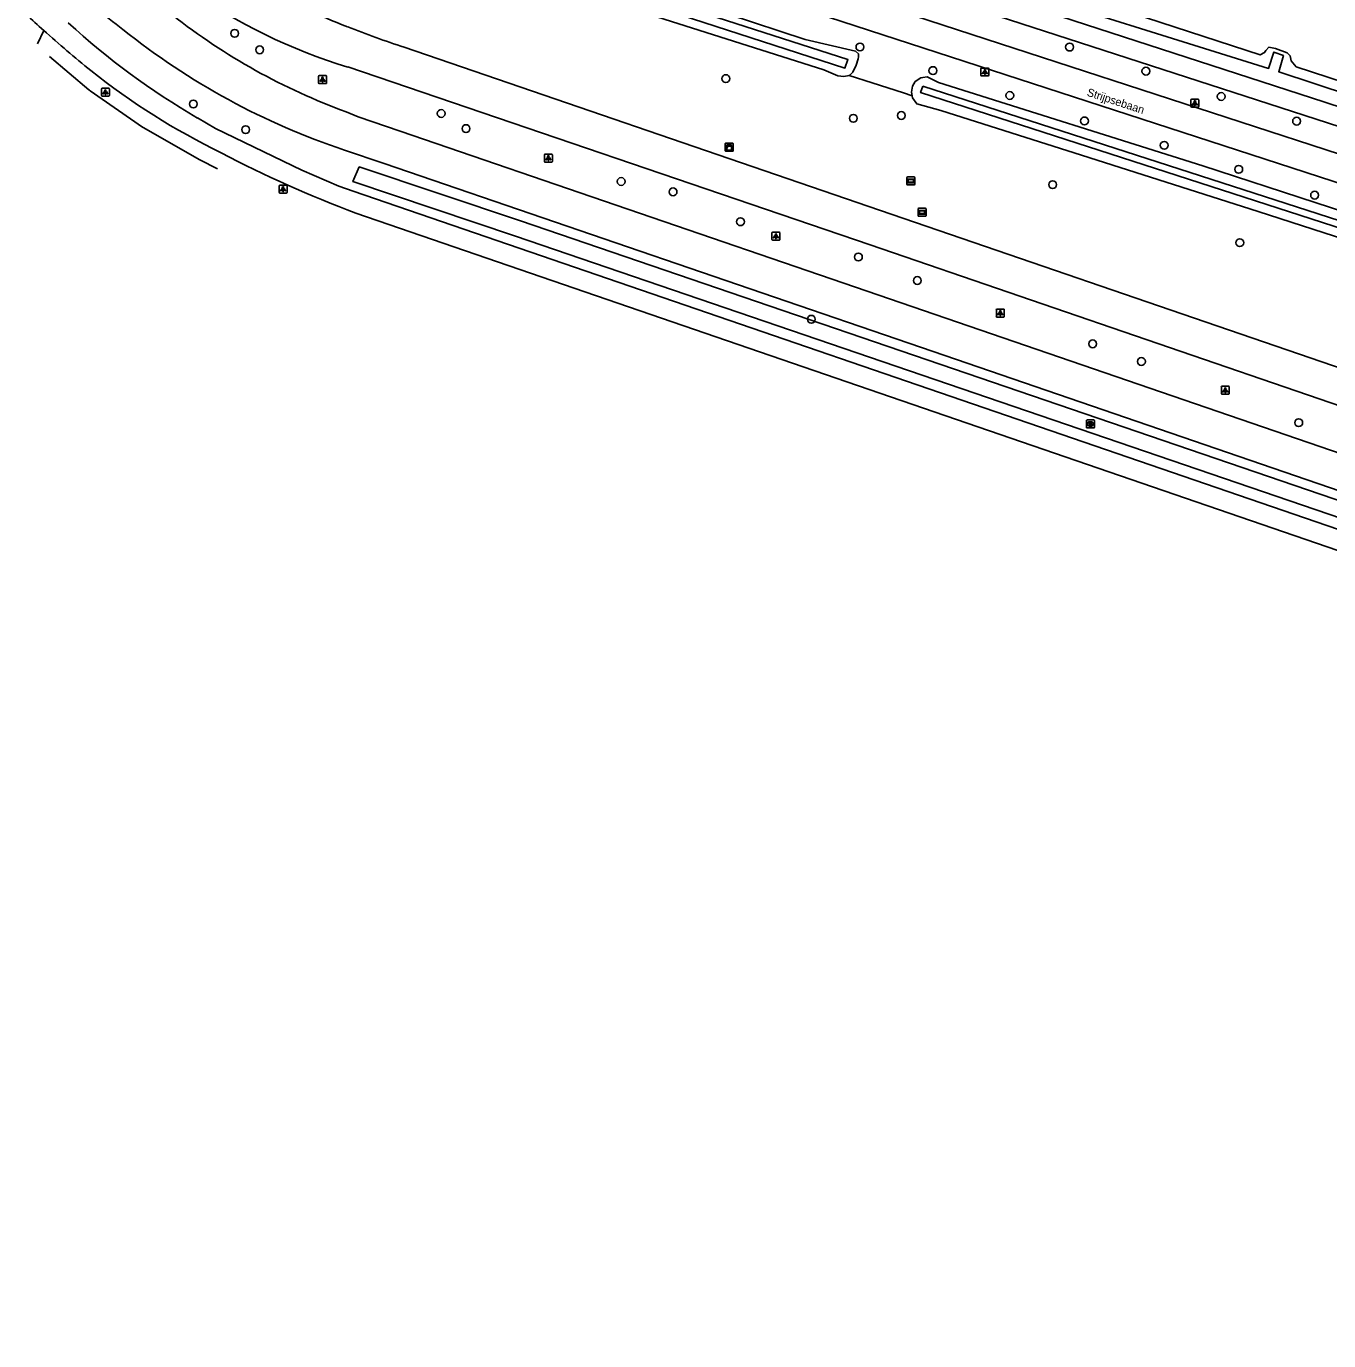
# Model space of a CAD drawing. Extents: x 155275 to 156263, y 382654 to 383635.
# Drawn here: x 155495 to 155657.8, y 382653.9 to 382818.2 of the extents above; entities that cross this region are included whole.
import ezdxf

# ---------------------------------------------------------------- set-up
doc = ezdxf.new("R2010")
doc.units = 0
for name, color, linetype in [('IMGEO_Berm_groen', 7, 'Continuous'), ('IMGEO_Boom', 7, 'Continuous'), ('IMGEO_Fietspad_gesloten', 7, 'Continuous'), ('IMGEO_Kast', 7, 'Continuous'), ('IMGEO_Kolk', 7, 'Continuous'), ('IMGEO_Lichtpunt', 7, 'Continuous'), ('IMGEO_Loofbos', 7, 'Continuous'), ('IMGEO_Muur', 7, 'Continuous'), ('IMGEO_Openbare_ruimte_label', 7, 'Continuous'), ('IMGEO_Rijbaan_regionaal_gesloten', 7, 'Continuous'), ('IMGEO_Verklikker', 7, 'Continuous'), ('IMGEO_Voetpad_open', 7, 'Continuous'), ('IMGEO_Waterloop', 7, 'Continuous')]:
    doc.layers.add(name, color=color, linetype=linetype)

msp = doc.modelspace()

# ---------------------------------------------------------------- linework, layer by layer
at = {"layer": 'IMGEO_Berm_groen'}
for points in [[(155509.58, 382844.19), (155511.11, 382843.85), (155513.91, 382843.18), (155517.02, 382842.15), (155533.94, 382835.74), (155534.62, 382835.53), (155592.37, 382816.51), (155598.66, 382815.05), (155599.06, 382814.71), (155599.04, 382814.32), (155599.02, 382814.11), (155598.74, 382813.29), (155598.34, 382812.43), (155597.96, 382812.03), (155597.87, 382812.01)], [(155597.87, 382812.01), (155597.2, 382811.87), (155596.45, 382811.96), (155594.7, 382812.71), (155573.04, 382819.6), (155561.92, 382822.84), (155552.11, 382826.24), (155542.74, 382829.39), (155531.1, 382833.59), (155523.88, 382835.91), (155514.69, 382838.61), (155507.83, 382840.77)], [(155577.78, 382834.26), (155577.59, 382833.89), (155577.45, 382833.38), (155577.38, 382832.64), (155577.38, 382832.6), (155577.58, 382832), (155578.91, 382831.42), (155583.98, 382830.01), (155915.89, 382722.43)], [(155605.76, 382809.46), (155604.65, 382809.83), (155600.76, 382811.07), (155597.87, 382812.01)], [(155605.76, 382809.46), (155605.67, 382809.92), (155605.8, 382810.69), (155606.13, 382811.25), (155606.85, 382811.72), (155607.09, 382811.75), (155607.61, 382811.82), (155609.02, 382811.14), (155642.06, 382800.7), (155726.29, 382773.22), (155732.73, 382771.2)], [(155732.16, 382768.19), (155728.25, 382769.37), (155649.01, 382795.02), (155626.9, 382802.04), (155609.34, 382807.63), (155606.33, 382808.48), (155605.81, 382809.2), (155605.76, 382809.46)]]:
    msp.add_lwpolyline(points, dxfattribs=at)
at = {"layer": 'IMGEO_Boom'}
for centre in [(155521.08, 382817.27), (155524.21, 382815.22), (155599.22, 382815.57), (155625.42, 382815.56), (155582.46, 382811.62), (155608.34, 382812.62), (155634.96, 382812.55), (155617.95, 382809.51), (155515.91, 382808.45), (155644.37, 382809.38), (155546.89, 382807.26), (155598.39, 382806.66), (155604.39, 382807.01), (155627.28, 382806.33), (155653.79, 382806.3), (155522.46, 382805.24), (155549.99, 382805.37), (155637.25, 382803.28), (155646.56, 382800.28), (155569.38, 382798.76), (155623.31, 382798.37), (155575.87, 382797.46), (155656.04, 382797.05), (155584.29, 382793.73), (155646.69, 382791.11), (155599.03, 382789.32), (155606.39, 382786.38), (155593.14, 382781.54), (155628.3, 382778.47), (155634.4, 382776.26), (155654.06, 382768.61)]:
    msp.add_circle(centre, 0.489, dxfattribs=at)
at = {"layer": 'IMGEO_Fietspad_gesloten'}
for points in [[(155900.91, 382719.83), (155759.67, 382765.92), (155663.46, 382797.12), (155571.34, 382827.15), (155557.35, 382831.56)], [(155902.12, 382723.09), (155736.56, 382777.11), (155664.54, 382800.41), (155572.37, 382830.46)], [(155496.43, 382815.95), (155497.22, 382817.65)], [(155516.42, 382806.7), (155518.7, 382805.4), (155529.49, 382800.17), (155534.1, 382798.16), (155535.88, 382797.55), (155896.95, 382673.55), (155947.87, 382656.21)], [(155536.23, 382794.8), (155803.62, 382702.94), (155946.67, 382653.88)]]:
    msp.add_lwpolyline(points, dxfattribs=at)
for centre, radius, start, end in [((155600.73, 382932.33), 154.49, 226.8323, 227.9305), ((155564.25, 382888.45), 94.72, 227.5243, 239.6755), ((155597.58, 382928.94), 149.86, 227.9558, 230.9139), ((155558.77, 382882.86), 89.63, 231.5993, 243.9509), ((155591.41, 382940.57), 155.87, 242.4879, 249.2664)]:
    msp.add_arc(centre, radius, start, end, dxfattribs=at)
at = {"layer": 'IMGEO_Kast'}
for p, q in [((155582.38, 382802.62), (155582.38, 382803.46)), ((155582.38, 382803.46), (155582.38, 382802.62)), ((155582.45, 382803.55), (155583.29, 382803.55)), ((155583.29, 382803.55), (155582.45, 382803.55)), ((155583.38, 382803.47), (155583.38, 382802.63)), ((155583.38, 382802.63), (155583.38, 382803.47)), ((155583.3, 382802.55), (155582.46, 382802.55)), ((155582.46, 382802.55), (155583.3, 382802.55))]:
    msp.add_line(p, q, dxfattribs=at)
for points in [[(155582.57, 382803.34), (155583.17, 382803.34), (155583.17, 382803.25), (155582.57, 382803.25), (155582.57, 382803.34)], [(155582.57, 382803.16), (155583.17, 382803.16), (155583.17, 382802.67), (155582.57, 382802.67), (155582.57, 382803.16)]]:
    msp.add_lwpolyline(points, dxfattribs=at)
msp.add_circle((155582.66, 382803.01), 0.0377, dxfattribs=at)
for centre, start, end in [((155582.46, 382803.47), 92.4484, 184.2845), ((155582.46, 382803.47), 92.4484, 184.2845), ((155583.3, 382803.47), 2.4484, 94.2845), ((155583.3, 382803.47), 2.4484, 94.2845), ((155582.46, 382802.62), 182.4484, 274.2845), ((155582.46, 382802.62), 182.4484, 274.2845), ((155583.3, 382802.62), 272.4484, 4.2845), ((155583.3, 382802.62), 272.4484, 4.2845)]:
    msp.add_arc(centre, 0.0779, start, end, dxfattribs=at)
at = {"layer": 'IMGEO_Kolk'}
for p, q in [((155627.6, 382768.96), (155628.45, 382768.96)), ((155627.53, 382768.04), (155627.53, 382768.89)), ((155628.45, 382767.96), (155627.6, 382767.96)), ((155628.01, 382768.74), (155628.04, 382768.74)), ((155628.04, 382768.18), (155628.01, 382768.18)), ((155628.53, 382768.89), (155628.53, 382768.04))]:
    msp.add_line(p, q, dxfattribs=at)
for points in [[(155627.6, 382768.96), (155628.45, 382768.96)], [(155627.53, 382768.04), (155627.53, 382768.89)], [(155628.45, 382767.96), (155627.6, 382767.96)], [(155627.85, 382768.66), (155627.97, 382768.66), (155627.97, 382768.51), (155628.1, 382768.66), (155628.26, 382768.66), (155628.12, 382768.51), (155628.27, 382768.26), (155628.12, 382768.26), (155628.03, 382768.43), (155627.97, 382768.36), (155627.97, 382768.26), (155627.85, 382768.26), (155627.85, 382768.66)], [(155628.53, 382768.89), (155628.53, 382768.04)]]:
    msp.add_lwpolyline(points, dxfattribs=at)
for centre, start, end in [((155627.6, 382768.89), 91.552, 178.448), ((155627.6, 382768.89), 91.552, 178.448), ((155628.45, 382768.89), 1.552, 88.448), ((155628.45, 382768.89), 1.552, 88.448), ((155627.6, 382768.04), 181.552, 268.448), ((155627.6, 382768.04), 181.552, 268.448), ((155628.45, 382768.04), 271.552, 358.448), ((155628.45, 382768.04), 271.552, 358.448)]:
    msp.add_arc(centre, 0.0765, start, end, dxfattribs=at)
for centre, major_axis, ratio, start_param, end_param in [((155628.01, 382768.46), (-0.387, 0.002), 0.722429, 4.712389, 7.853982), ((155628.04, 382768.46), (-0.39, 0.002), 0.717154, 1.570796, 4.712389)]:
    msp.add_ellipse(centre, major_axis=major_axis, ratio=ratio, start_param=start_param, end_param=end_param, dxfattribs=at)
at = {"layer": 'IMGEO_Lichtpunt'}
for p, q in [((155531.56, 382811.9), (155531.56, 382811.09)), ((155531.56, 382811.9), (155531.56, 382811.09)), ((155532.47, 382811.99), (155531.66, 382811.99)), ((155532.47, 382811.99), (155531.66, 382811.99)), ((155532.56, 382811.09), (155532.56, 382811.9)), ((155532.56, 382811.09), (155532.56, 382811.9)), ((155614.34, 382812.85), (155614.34, 382812.04)), ((155614.34, 382812.85), (155614.34, 382812.04)), ((155615.24, 382812.94), (155614.43, 382812.94)), ((155615.24, 382812.94), (155614.43, 382812.94)), ((155614.43, 382811.95), (155615.24, 382811.95)), ((155614.43, 382811.95), (155615.24, 382811.95)), ((155615.33, 382812.04), (155615.33, 382812.85)), ((155615.33, 382812.04), (155615.33, 382812.85)), ((155504.43, 382810.33), (155504.43, 382809.52)), ((155504.43, 382810.33), (155504.43, 382809.52)), ((155505.34, 382810.42), (155504.53, 382810.42)), ((155505.34, 382810.42), (155504.53, 382810.42)), ((155505.43, 382809.52), (155505.43, 382810.33)), ((155505.43, 382809.52), (155505.43, 382810.33)), ((155531.66, 382810.99), (155532.47, 382810.99)), ((155531.66, 382810.99), (155532.47, 382810.99)), ((155504.53, 382809.42), (155505.34, 382809.42)), ((155504.53, 382809.42), (155505.34, 382809.42)), ((155640.58, 382808.95), (155640.58, 382808.14)), ((155640.58, 382808.95), (155640.58, 382808.14)), ((155641.48, 382809.04), (155640.67, 382809.04)), ((155641.48, 382809.04), (155640.67, 382809.04)), ((155641.57, 382808.14), (155641.57, 382808.95)), ((155641.57, 382808.14), (155641.57, 382808.95)), ((155640.67, 382808.05), (155641.48, 382808.05)), ((155640.67, 382808.05), (155641.48, 382808.05)), ((155559.78, 382802.08), (155559.78, 382801.27)), ((155559.78, 382802.08), (155559.78, 382801.27)), ((155560.69, 382802.18), (155559.88, 382802.18)), ((155560.69, 382802.18), (155559.88, 382802.18)), ((155560.78, 382801.27), (155560.78, 382802.08)), ((155560.78, 382801.27), (155560.78, 382802.08)), ((155559.88, 382801.18), (155560.69, 382801.18)), ((155559.88, 382801.18), (155560.69, 382801.18)), ((155526.63, 382798.21), (155526.63, 382797.4)), ((155526.63, 382798.21), (155526.63, 382797.4)), ((155527.54, 382798.31), (155526.73, 382798.31)), ((155527.54, 382798.31), (155526.73, 382798.31)), ((155526.73, 382797.31), (155527.54, 382797.31)), ((155526.73, 382797.31), (155527.54, 382797.31)), ((155527.63, 382797.4), (155527.63, 382798.21)), ((155527.63, 382797.4), (155527.63, 382798.21)), ((155588.23, 382792.32), (155588.23, 382791.52)), ((155588.23, 382792.32), (155588.23, 382791.52)), ((155589.13, 382792.42), (155588.32, 382792.42)), ((155589.13, 382792.42), (155588.32, 382792.42)), ((155589.22, 382791.52), (155589.22, 382792.32)), ((155589.22, 382791.52), (155589.22, 382792.32)), ((155588.32, 382791.42), (155589.13, 382791.42)), ((155588.32, 382791.42), (155589.13, 382791.42)), ((155616.27, 382782.72), (155616.27, 382781.91)), ((155616.27, 382782.72), (155616.27, 382781.91)), ((155617.17, 382782.81), (155616.36, 382782.81)), ((155617.17, 382782.81), (155616.36, 382782.81)), ((155617.26, 382781.91), (155617.26, 382782.72)), ((155617.26, 382781.91), (155617.26, 382782.72)), ((155616.36, 382781.81), (155617.17, 382781.81)), ((155616.36, 382781.81), (155617.17, 382781.81)), ((155644.39, 382773.07), (155644.39, 382772.27)), ((155644.39, 382773.07), (155644.39, 382772.27)), ((155645.29, 382773.17), (155644.48, 382773.17)), ((155645.29, 382773.17), (155644.48, 382773.17)), ((155645.38, 382772.27), (155645.38, 382773.07)), ((155645.38, 382772.27), (155645.38, 382773.07)), ((155644.48, 382772.17), (155645.29, 382772.17)), ((155644.48, 382772.17), (155645.29, 382772.17))]:
    msp.add_line(p, q, dxfattribs=at)
for points in [[(155614.71, 382812.51), (155614.75, 382812.49), (155614.56, 382812.22), (155614.52, 382812.25), (155614.71, 382812.51)], [(155614.81, 382812.47), (155614.86, 382812.47), (155614.86, 382812.14), (155614.81, 382812.14), (155614.81, 382812.47)], [(155614.92, 382812.49), (155614.96, 382812.51), (155615.15, 382812.25), (155615.11, 382812.22), (155614.92, 382812.49)], [(155504.81, 382809.99), (155504.85, 382809.96), (155504.66, 382809.7), (155504.62, 382809.73), (155504.81, 382809.99)], [(155505.02, 382809.96), (155505.06, 382809.99), (155505.25, 382809.73), (155505.21, 382809.7), (155505.02, 382809.96)], [(155531.94, 382811.56), (155531.98, 382811.53), (155531.79, 382811.27), (155531.75, 382811.3), (155531.94, 382811.56)], [(155532.04, 382811.51), (155532.09, 382811.51), (155532.09, 382811.19), (155532.04, 382811.19), (155532.04, 382811.51)], [(155532.15, 382811.53), (155532.19, 382811.56), (155532.38, 382811.3), (155532.34, 382811.27), (155532.15, 382811.53)], [(155504.91, 382809.94), (155504.96, 382809.94), (155504.96, 382809.62), (155504.91, 382809.62), (155504.91, 382809.94)], [(155640.95, 382808.61), (155640.99, 382808.59), (155640.8, 382808.32), (155640.76, 382808.35), (155640.95, 382808.61)], [(155641.05, 382808.57), (155641.1, 382808.57), (155641.1, 382808.24), (155641.05, 382808.24), (155641.05, 382808.57)], [(155641.16, 382808.59), (155641.2, 382808.61), (155641.39, 382808.35), (155641.35, 382808.32), (155641.16, 382808.59)], [(155560.16, 382801.74), (155560.2, 382801.72), (155560.01, 382801.45), (155559.97, 382801.48), (155560.16, 382801.74)], [(155560.26, 382801.7), (155560.31, 382801.7), (155560.31, 382801.37), (155560.26, 382801.37), (155560.26, 382801.7)], [(155560.37, 382801.72), (155560.41, 382801.74), (155560.6, 382801.48), (155560.56, 382801.45), (155560.37, 382801.72)], [(155527.01, 382797.87), (155527.05, 382797.85), (155526.86, 382797.58), (155526.82, 382797.61), (155527.01, 382797.87)], [(155527.11, 382797.83), (155527.16, 382797.83), (155527.16, 382797.5), (155527.11, 382797.5), (155527.11, 382797.83)], [(155527.22, 382797.85), (155527.26, 382797.87), (155527.45, 382797.61), (155527.41, 382797.58), (155527.22, 382797.85)], [(155588.6, 382791.99), (155588.64, 382791.96), (155588.45, 382791.7), (155588.41, 382791.72), (155588.6, 382791.99)], [(155588.7, 382791.94), (155588.75, 382791.94), (155588.75, 382791.62), (155588.7, 382791.62), (155588.7, 382791.94)], [(155588.81, 382791.96), (155588.85, 382791.99), (155589.04, 382791.72), (155589, 382791.7), (155588.81, 382791.96)], [(155616.64, 382782.38), (155616.68, 382782.35), (155616.49, 382782.09), (155616.45, 382782.12), (155616.64, 382782.38)], [(155616.74, 382782.33), (155616.79, 382782.33), (155616.79, 382782.01), (155616.74, 382782.01), (155616.74, 382782.33)], [(155616.85, 382782.35), (155616.89, 382782.38), (155617.08, 382782.12), (155617.04, 382782.09), (155616.85, 382782.35)], [(155644.76, 382772.74), (155644.8, 382772.71), (155644.61, 382772.45), (155644.57, 382772.47), (155644.76, 382772.74)], [(155644.86, 382772.69), (155644.91, 382772.69), (155644.91, 382772.37), (155644.86, 382772.37), (155644.86, 382772.69)], [(155644.97, 382772.71), (155645.01, 382772.74), (155645.2, 382772.47), (155645.16, 382772.45), (155644.97, 382772.71)]]:
    msp.add_lwpolyline(points, dxfattribs=at)
for centre in [(155532.06, 382811.69), (155614.84, 382812.65), (155504.93, 382810.12), (155641.08, 382808.75), (155560.28, 382801.88), (155527.13, 382798.01), (155588.73, 382792.12), (155616.77, 382782.51), (155644.89, 382772.87)]:
    msp.add_circle(centre, 0.0994, dxfattribs=at)
for centre, start, end in [((155531.66, 382811.9), 90, 180), ((155531.66, 382811.9), 90, 180), ((155532.47, 382811.9), 0, 90), ((155532.47, 382811.9), 0, 90), ((155614.43, 382812.85), 90, 180), ((155614.43, 382812.85), 90, 180), ((155614.43, 382812.04), 180, 270), ((155614.43, 382812.04), 180, 270), ((155615.24, 382812.85), 0, 90), ((155615.24, 382812.85), 0, 90), ((155615.24, 382812.04), 270, 0), ((155615.24, 382812.04), 270, 360), ((155504.53, 382810.33), 90, 180), ((155504.53, 382810.33), 90, 180), ((155505.34, 382810.33), 0, 90), ((155505.34, 382810.33), 0, 90), ((155531.66, 382811.09), 180, 270), ((155531.66, 382811.09), 180, 270), ((155532.47, 382811.09), 270, 0), ((155532.47, 382811.09), 270, 360), ((155504.53, 382809.52), 180, 270), ((155504.53, 382809.52), 180, 270), ((155505.34, 382809.52), 270, 0), ((155505.34, 382809.52), 270, 360), ((155640.67, 382808.95), 90, 180), ((155640.67, 382808.95), 90, 180), ((155641.48, 382808.95), 0, 90), ((155641.48, 382808.95), 0, 90), ((155640.67, 382808.14), 180, 270), ((155640.67, 382808.14), 180, 270), ((155641.48, 382808.14), 270, 0), ((155641.48, 382808.14), 270, 360), ((155559.88, 382802.08), 90, 180), ((155559.88, 382802.08), 90, 180), ((155560.69, 382802.08), 0, 90), ((155560.69, 382802.08), 0, 90), ((155559.88, 382801.27), 180, 270), ((155559.88, 382801.27), 180, 270), ((155560.69, 382801.27), 270, 0), ((155560.69, 382801.27), 270, 360), ((155526.73, 382798.21), 90, 180), ((155526.73, 382798.21), 90, 180), ((155526.73, 382797.4), 180, 270), ((155526.73, 382797.4), 180, 270), ((155527.54, 382798.21), 0, 90), ((155527.54, 382798.21), 0, 90), ((155527.54, 382797.4), 270, 0), ((155527.54, 382797.4), 270, 360), ((155588.32, 382792.32), 90, 180), ((155588.32, 382792.32), 90, 180), ((155589.13, 382792.32), 0, 90), ((155589.13, 382792.32), 0, 90), ((155588.32, 382791.52), 180, 270), ((155588.32, 382791.52), 180, 270), ((155589.13, 382791.52), 270, 0), ((155589.13, 382791.52), 270, 360), ((155616.36, 382782.72), 90, 180), ((155616.36, 382782.72), 90, 180), ((155617.17, 382782.72), 0, 90), ((155617.17, 382782.72), 0, 90), ((155616.36, 382781.91), 180, 270), ((155616.36, 382781.91), 180, 270), ((155617.17, 382781.91), 270, 0), ((155617.17, 382781.91), 270, 360), ((155644.48, 382773.07), 90, 180), ((155644.48, 382773.07), 90, 180), ((155644.48, 382772.27), 180, 270), ((155644.48, 382772.27), 180, 270), ((155645.29, 382773.07), 0, 90), ((155645.29, 382773.07), 0, 90), ((155645.29, 382772.27), 270, 0), ((155645.29, 382772.27), 270, 360)]:
    msp.add_arc(centre, 0.0946, start, end, dxfattribs=at)
at = {"layer": 'IMGEO_Loofbos'}
msp.add_lwpolyline([(155599.34, 382830.86), (155649.23, 382814.57), (155649.8, 382814.87), (155649.96, 382815.14), (155650.32, 382815.53), (155651.15, 382815.37), (155652.6, 382814.82), (155653, 382814.45), (155653.11, 382813.83), (155653.75, 382813.09), (155916.37, 382727.37)], dxfattribs=at)
at = {"layer": 'IMGEO_Muur'}
msp.add_lwpolyline([(155651.56, 382812.47), (155652.14, 382814.5), (155650.94, 382814.93), (155650.3, 382812.89)], dxfattribs=at)
at = {"layer": 'IMGEO_Rijbaan_regionaal_gesloten'}
for points in [[(155956.56, 382673.18), (155938.56, 382679.65), (155542.28, 382815.54)], [(155535.22, 382813.07), (155600.48, 382790.85), (155937.17, 382675.36), (155954.48, 382669.13)], [(155952.14, 382664.55), (155935.54, 382669.94), (155598.66, 382785.57), (155541.77, 382805.05), (155536.5, 382806.83), (155535.02, 382807.46)], [(155534.82, 382802.68), (155539.76, 382800.99), (155608.36, 382777.52), (155933.83, 382665.8), (155950.07, 382660.52)]]:
    msp.add_lwpolyline(points, dxfattribs=at)
for centre, radius, start, end in [((155547.07, 382872.02), 67.37, 226.2669, 233.632), ((155555, 382878.56), 68.42, 234.5815, 253.194), ((155561.8, 382886.22), 73.15, 239.6722, 248.6751), ((155562.09, 382881.56), 78.89, 231.7942, 249.9386), ((155563, 382887.37), 89.26, 231.239, 251.5986), ((155577.22, 382923.79), 113.75, 248.3239, 252.1122)]:
    msp.add_arc(centre, radius, start, end, dxfattribs=at)
at = {"layer": 'IMGEO_Verklikker'}
for p, q in [((155605.09, 382798.43), (155605.09, 382799.23)), ((155605.09, 382799.23), (155605.09, 382798.43)), ((155605.19, 382799.33), (155605.98, 382799.33)), ((155605.98, 382799.33), (155605.19, 382799.33)), ((155606.08, 382799.23), (155606.08, 382798.43)), ((155606.08, 382798.43), (155606.08, 382799.23)), ((155605.98, 382798.33), (155605.19, 382798.33)), ((155605.19, 382798.33), (155605.98, 382798.33)), ((155606.49, 382794.51), (155606.49, 382795.31)), ((155606.49, 382795.31), (155606.49, 382794.51)), ((155606.59, 382795.41), (155607.38, 382795.41)), ((155607.38, 382795.41), (155606.59, 382795.41)), ((155607.48, 382795.31), (155607.48, 382794.51)), ((155607.48, 382794.51), (155607.48, 382795.31)), ((155607.38, 382794.41), (155606.59, 382794.41)), ((155606.59, 382794.41), (155607.38, 382794.41))]:
    msp.add_line(p, q, dxfattribs=at)
for points in [[(155605.2, 382799.07), (155605.98, 382799.07), (155605.98, 382798.6), (155605.2, 382798.6), (155605.2, 382799.07)], [(155605.26, 382799), (155605.26, 382798.67), (155605.92, 382798.67), (155605.92, 382799), (155605.26, 382799)], [(155606.59, 382795.15), (155607.38, 382795.15), (155607.38, 382794.68), (155606.59, 382794.68), (155606.59, 382795.15)], [(155606.65, 382795.08), (155606.65, 382794.75), (155607.31, 382794.75), (155607.31, 382795.08), (155606.65, 382795.08)]]:
    msp.add_lwpolyline(points, dxfattribs=at)
for centre, start, end in [((155605.19, 382799.23), 90, 180), ((155605.19, 382799.23), 90, 180), ((155605.98, 382799.23), 0, 90), ((155605.98, 382799.23), 360, 90), ((155605.19, 382798.43), 180, 270), ((155605.19, 382798.43), 180, 270), ((155605.98, 382798.43), 270, 0), ((155605.98, 382798.43), 270, 0), ((155606.59, 382795.31), 90, 180), ((155606.59, 382795.31), 90, 180), ((155607.38, 382795.31), 0, 90), ((155607.38, 382795.31), 360, 90), ((155606.59, 382794.51), 180, 270), ((155606.59, 382794.51), 180, 270), ((155607.38, 382794.51), 270, 0), ((155607.38, 382794.51), 270, 0)]:
    msp.add_arc(centre, 0.1, start, end, dxfattribs=at)
at = {"layer": 'IMGEO_Voetpad_open'}
msp.add_lwpolyline([(155497.92, 382814.39), (155502.87, 382810.23), (155502.95, 382810.17), (155503.04, 382810.1), (155509.55, 382805.57), (155509.64, 382805.5), (155516.73, 382801.46), (155518.92, 382800.36)], dxfattribs=at)
at = {"layer": 'IMGEO_Waterloop'}
for points in [[(155507.93, 382842.69), (155507.7, 382842.01), (155597.34, 382812.93), (155597.72, 382813.99), (155518.16, 382839.64), (155516.75, 382840.03), (155507.93, 382842.69)], [(155686.43, 382799.15), (155657.3, 382808.66), (155583.39, 382832.73), (155579.52, 382833.86), (155578.34, 382834.31), (155578.74, 382835.28), (155579.86, 382834.91), (155650.3, 382812.89), (155650.94, 382814.93), (155652.14, 382814.5), (155651.56, 382812.47), (155910.7, 382726.88)], [(155607.07, 382810.69), (155606.81, 382809.88), (155732.39, 382769.25), (155732.6, 382770.14), (155607.07, 382810.69)], [(155762.76, 382723.32), (155814.14, 382705.55), (155866.08, 382687.83), (155944.89, 382660.79), (155944.25, 382658.9), (155865.43, 382685.94), (155813.49, 382703.65), (155762.11, 382721.43), (155657.81, 382757.19), (155556.16, 382791.94), (155535.86, 382798.75), (155536.64, 382800.59), (155556.8, 382793.83), (155658.45, 382759.09), (155762.76, 382723.32)]]:
    msp.add_lwpolyline(points, dxfattribs=at)

# ---------------------------------------------------------------- texts
at = {"layer": 'IMGEO_Openbare_ruimte_label'}
msp.add_text('Strijpsebaan', height=1, rotation=341.8732, dxfattribs=at).set_placement((155627.51, 382809.5))

doc.saveas('drawing.dxf')
